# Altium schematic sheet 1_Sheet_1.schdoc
size 426 x 302 mm; Name: A_A3; Symbol: A_A3; Device: A_A3; @Project Name: FRBC - USB interface V4; REV: 4; Date: 2025-04-17; Sheet: 1/1; Draw By: JJ Shapiro; Company: SHAPIRO; Convert to PCB: yes; Add into BOM: yes; spicePre: .; @Page No: 1; @Page Count: 1; @Schematic Name: FRBC - USB interface_1; @Board Name: FRBC - USB interface_1; @Update Date: 2025-07-15; @Create Time: 17:14:42; @Update Time: 18:14:42; @Page Name: Sheet_1; @Create Date: 2025-07-15
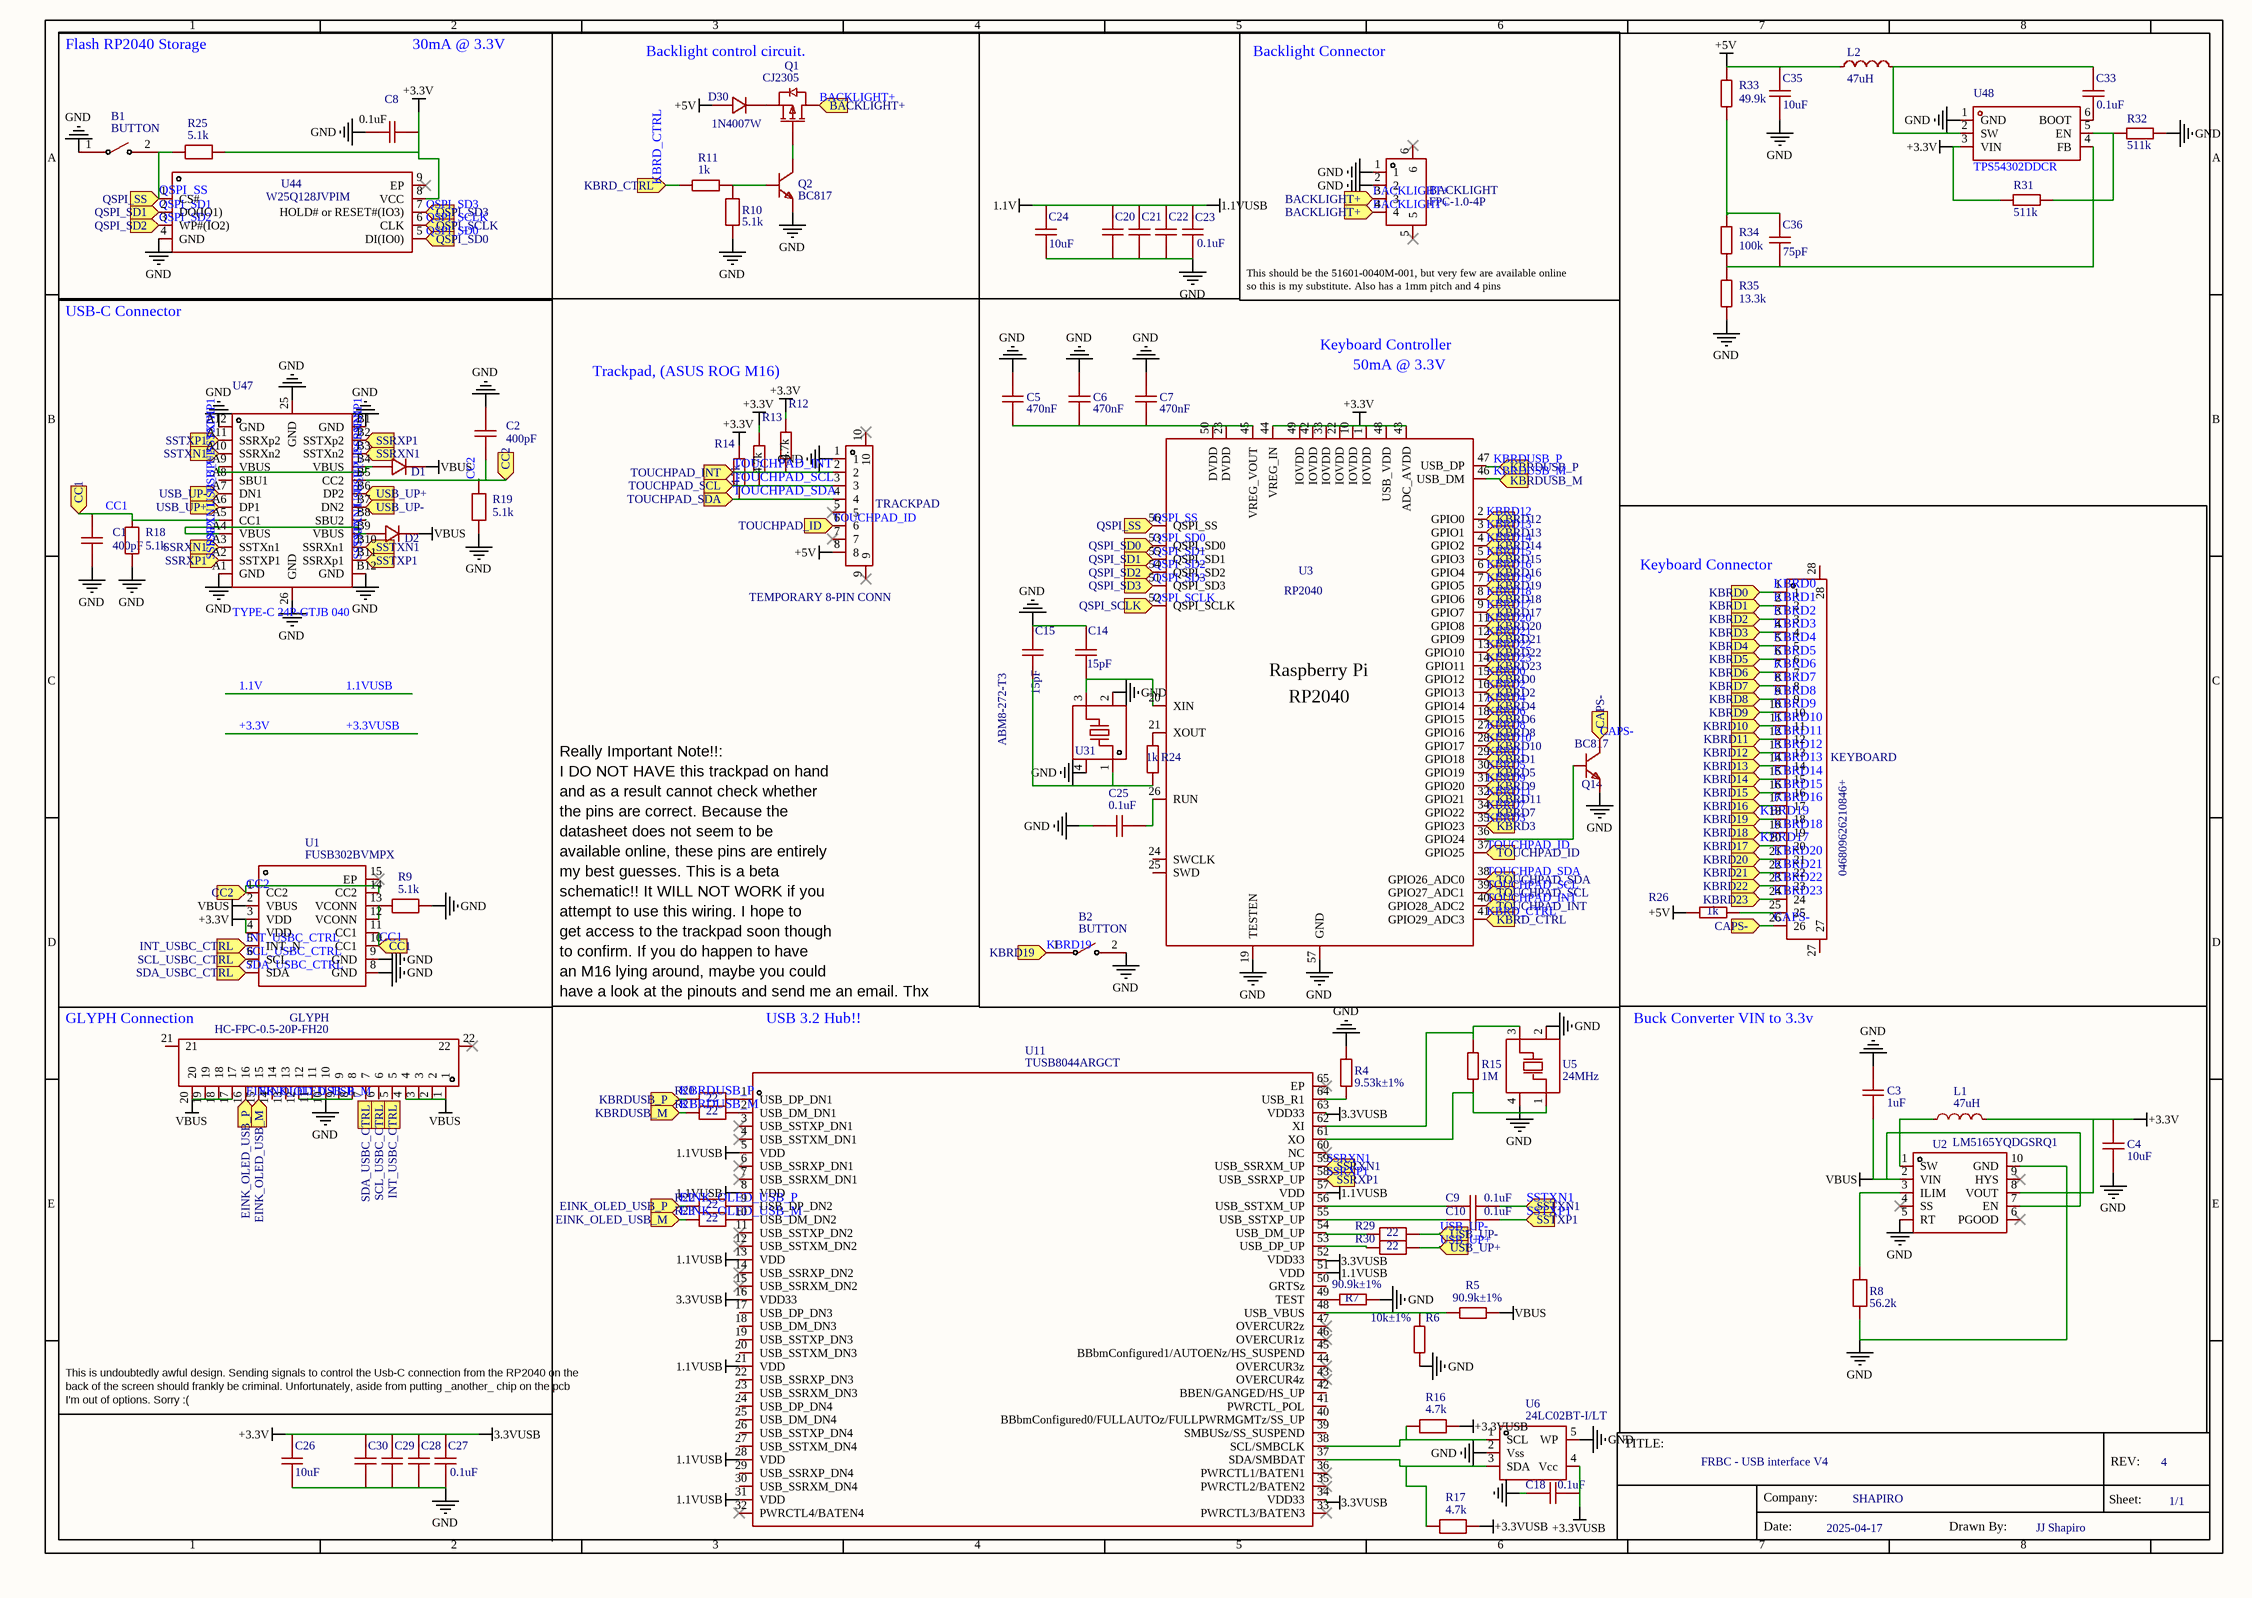
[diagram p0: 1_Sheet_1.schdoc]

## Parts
B1  BUTTON  [SW-SMD_L3.9-W2.9-LS4.9-L]
B2  BUTTON  [SW-SMD_L3.9-W2.9-LS4.9-L]
BACKLIGHT  FPC-1.0-4P  [FPC-SMD_4P-P1.00_HDGC_1.0K-ES-4PWB]
C1  400pF  [C0402]
C2  400pF  [C0402]
C3  1uF  [C0402]
C4  10uF  [C0402]
C5  470nF  [C0402]
C6  470nF  [C0402]
C7  470nF  [C0402]
C8  0.1uF  [C0402]  (value not drawn)
C9  0.1uF  [C0402]
C10  0.1uF  [C0402]
C14  15pF  [C0402]
C15  15pF  [C0402]
C18  0.1uF  [C0402]
C20  0.1uF  [C0402]  (value not drawn)
C21  0.1uF  [C0402]  (value not drawn)
C22  0.1uF  [C0402]  (value not drawn)
C23  0.1uF  [C0402]
C24  10uF  [C0402]
C25  0.1uF  [C0402]
C26  10uF  [C0402]
C27  0.1uF  [C0402]
C28  0.1uF  [C0402]  (value not drawn)
C29  0.1uF  [C0402]  (value not drawn)
C30  0.1uF  [C0402]  (value not drawn)
C33  0.1uF  [C0402]
C35  10uF  [C0402]
C36  75pF  [C0402]
D1  1N4007W  [SOD-123_L2.8-W1.8-LS3.7-RD]  (value not drawn)
D2  1N4007W  [SOD-123_L2.8-W1.8-LS3.7-RD]  (value not drawn)
D30  1N4007W  [SOD-123_L2.8-W1.8-LS3.7-RD]
GLYPH  HC-FPC-0.5-20P-FH20  [FPC-SMD_20P-P0.50_HC-FPC-0.5-20P-FH20]
KEYBOARD  046809626210846+  [FPC-SMD_26P-P0.50_046809626210846]
L1  47uH  [L0603]
L2  47uH  [L0603]
Q1  CJ2305  [SOT-23-3_L2.9-W1.3-P1.90-LS2.4-BR]
Q2  BC817  [SOT-23-3_L2.9-W1.3-P1.90-LS2.4-BR]
Q14  BC817  [SOT-23-3_L2.9-W1.3-P1.90-LS2.4-BR]
R4  9.53k±1%  [R0603]
R5  90.9k±1%  [R0603]
R6  10k±1%  [R0603]
R7  90.9k±1%  [R0603]
R8  56.2k  [R0402]
R9  5.1k  [R0402]
R10  5.1k  [R0402]
R11  1k  [R0402]
R12  4.7k - 0603  [R0402]  (value not drawn)
R13  4.7k - 0603  [R0402]  (value not drawn)
R14  4.7k  [R0402]
R15  1M  [R0603]
R16  4.7k  [R0402]
R17  4.7k  [R0402]
R18  5.1k  [R0402]
R19  5.1k  [R0402]
R20  22  [R0402]
R21  22  [R0402]
R22  22  [R0402]
R23  22  [R0402]
R24  1k  [R0402]
R25  5.1k  [R0402]
R26  1k  [R0402]
R29  22  [R0402]
R30  22  [R0402]
R31  511k  [R0603]
R32  511k  [R0603]
R33  49.9k  [R0603]
R34  100k  [R0603]
R35  13.3k  [R0603]
TRACKPAD  TEMPORARY 8-PIN CONN  [CONN-SMD_8P-P0.50_HC-FPC-0.5-8P-FHH20]
U1  FUSB302BVMPX  [MLP-14_L2.5-W2.5-P0.50-BL-EP]
U2  LM5165YQDGSRQ1  [VSSOP-10_L3.0-W3.0-P0.50-LS4.9-BL]
U3  RP2040  [LQFN-56_L7.0-W7.0-P0.4-EP]
U5  24MHz  [OSC-SMD_4P-XRCGB24M000F0L00R0]
U6  24LC02BT-I/LT  [SC-70-5_L2.0-W1.3-P0.65-LS2.1-BR]
U11  TUSB8044ARGCT  [VQFN-64_L9.0-W9.0-P0.50-TL-EP5.8]
U31  ABM8-272-T3  [CRYSTAL-SMD_4P-L3.2-W2.5-BL-2]
U44  W25Q128JVPIM  [WSON-8_L5.0-W6.0-P1.27-BL-EP]
U47  TYPE-C 24P-GTJB 040  [USB-C-SMD_TYPE-C-24P-GTJB-040]
U48  TPS54302DDCR  [SOT-23-6_L2.9-W1.6-P0.95-LS2.8-BL]

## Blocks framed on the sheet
Backlight control circuit.: D30 Q1 Q2 R10 R11
Backlight Connector: BACKLIGHT
USB-C Connector: C1 C2 D1 D2 R9 R18 R19 U1 U47
Keyboard Connector: KEYBOARD R26
Buck Converter VIN to 3.3v: C3 C4 L1 R8 U2

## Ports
BACKLIGHT+ (in), CAPS- (in), CC1 (in), CC2 (in), EINK_OLED_USB_M (in), EINK_OLED_USB_P (in), INT_USBC_CTRL (in), KBRD0 (in), KBRD1 (in), KBRD2 (in), KBRD3 (in), KBRD4 (in), KBRD5 (in), KBRD6 (in), KBRD7 (in), KBRD8 (in), KBRD9 (in), KBRD10 (in), KBRD11 (in), KBRD12 (in), KBRD13 (in), KBRD14 (in), KBRD15 (in), KBRD16 (in), KBRD17 (in), KBRD18 (in), KBRD19 (in), KBRD20 (in), KBRD21 (in), KBRD22 (in), KBRD23 (in), KBRD_CTRL (in), KBRDUSB_M (in), KBRDUSB_P (in), QSPI_SCLK (in), QSPI_SD0 (in), QSPI_SD1 (in), QSPI_SD2 (in), QSPI_SD3 (in), QSPI_SS (in), SCL_USBC_CTRL (in), SDA_USBC_CTRL (in), SSRXN1 (in), SSRXP1 (in), SSTXN1 (in), SSTXP1 (in), TOUCHPAD_ID (in), TOUCHPAD_INT (in), TOUCHPAD_SCL (in), TOUCHPAD_SDA (in), USB_UP+ (in), USB_UP- (in)

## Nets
1.1V: C20.2 C21.2 C22.2 C23.2 C24.2 U11.5(VDD) U11.8(VDD) U11.13(VDD) U11.21(VDD) U11.28(VDD) U11.31(VDD) U11.51(VDD) U11.57(VDD)  [also labelled 1.1VUSB]
+3.3V: C4.2 C8.1 C18.1 C26.2 C27.2 C28.2 C29.2 C30.2 L1.2 R12.1 R13.1 R14.1 R16.2 R17.2 R25.1 R31.2 U1.3(VDD) U1.4(VDD) U2.8(VOUT) U3.1(IOVDD) U3.10(IOVDD) U3.22(IOVDD) U3.33(IOVDD) U3.42(IOVDD) U3.43(ADC_AVDD) U3.44(VREG_IN) U3.48(USB_VDD) U3.49(IOVDD) U6.4(Vcc) U11.16(VDD33) U11.34(VDD33) U11.52(VDD33) U11.63(VDD33) U44.8(VCC) U48.3(VIN)  [also labelled +3.3VUSB, 3.3VUSB]
+5V: C35.2 D30.2 L2.1 R26.2 R33.1 TRACKPAD.8
GND: B1.1 B2.2 BACKLIGHT.1 BACKLIGHT.2 C1.1 C2.2 C3.2 C4.1 C5.2 C6.2 C7.2 C8.2 C14.1 C15.1 C18.2 C20.1 C21.1 C22.1 C23.1 C24.1 C25.2 C26.1 C27.1 C28.1 C29.1 C30.1 C35.1 GLYPH.8 GLYPH.9 GLYPH.10 GLYPH.11 GLYPH.12 Q2.2(E) Q14.2(E) R4.1 R6.2 R7.1 R8.1 R9.2 R10.1 R18.1 R19.1 R32.1 R35.2 TRACKPAD.1 U1.8(GND) U1.9(GND) U2.5(RT) U2.10(GND) U3.19(TESTEN) U3.57(GND) U5.2(GND) U5.4(GND) U6.2(Vss) U6.5(WP) U31.2(GND) U31.4(GND) U44.4(GND) U47.25(GND) U47.26(GND) U47.A1(GND) U47.A12(GND) U47.B1(GND) U47.B12(GND) U48.1(GND)
VBUS: C3.1 D1.1 D2.1 GLYPH.1 GLYPH.2 GLYPH.3 GLYPH.4 GLYPH.17 GLYPH.18 GLYPH.19 GLYPH.20 R5.1 U1.2(VBUS) U2.2(VIN) U2.7(EN)
BACKLIGHT+: BACKLIGHT.3 BACKLIGHT.4 Q1.3(D) ; port BACKLIGHT+
CAPS-: KEYBOARD.26 Q14.3(C) ; port CAPS-
CC1: C1.2 R18.2 U1.10(CC1) U1.11(CC1) U47.A5(CC1) ; port CC1
CC2: C2.1 R19.2 U1.1(CC2) U1.14(CC2) U47.B5(CC2) ; port CC2
EINK_OLED_USB_M: GLYPH.15 R23.1 ; port EINK_OLED_USB_M
EINK_OLED_USB_P: GLYPH.16 R22.1 ; port EINK_OLED_USB_P
INT_USBC_CTRL: U1.5(INT_N) ; port INT_USBC_CTRL
KBRD0: KEYBOARD.1 U3.15(GPIO12) ; port KBRD0
KBRD1: KEYBOARD.2 U3.29(GPIO18) ; port KBRD1
KBRD2: KEYBOARD.3 U3.16(GPIO13) ; port KBRD2
KBRD3: KEYBOARD.4 U3.35(GPIO23) ; port KBRD3
KBRD4: KEYBOARD.5 U3.17(GPIO14) ; port KBRD4
KBRD5: KEYBOARD.6 U3.30(GPIO19) ; port KBRD5
KBRD6: KEYBOARD.7 U3.18(GPIO15) ; port KBRD6
KBRD7: KEYBOARD.8 U3.34(GPIO22) ; port KBRD7
KBRD8: KEYBOARD.9 U3.27(GPIO16) ; port KBRD8
KBRD9: KEYBOARD.10 U3.31(GPIO20) ; port KBRD9
KBRD10: KEYBOARD.11 U3.28(GPIO17) ; port KBRD10
KBRD11: KEYBOARD.12 U3.32(GPIO21) ; port KBRD11
KBRD12: KEYBOARD.13 U3.2(GPIO0) ; port KBRD12
KBRD13: KEYBOARD.14 U3.3(GPIO1) ; port KBRD13
KBRD14: KEYBOARD.15 U3.4(GPIO2) ; port KBRD14
KBRD15: KEYBOARD.16 U3.5(GPIO3) ; port KBRD15
KBRD16: KEYBOARD.17 U3.6(GPIO4) ; port KBRD16
KBRD17: KEYBOARD.20 U3.9(GPIO7) ; port KBRD17
KBRD18: KEYBOARD.19 U3.8(GPIO6) ; port KBRD18
KBRD19: B2.1 KEYBOARD.18 U3.7(GPIO5) ; port KBRD19
KBRD20: KEYBOARD.21 U3.11(GPIO8) ; port KBRD20
KBRD21: KEYBOARD.22 U3.12(GPIO9) ; port KBRD21
KBRD22: KEYBOARD.23 U3.13(GPIO10) ; port KBRD22
KBRD23: KEYBOARD.24 U3.14(GPIO11) ; port KBRD23
KBRD_CTRL: R11.1 U3.41(GPIO29_ADC3) ; port KBRD_CTRL
KBRDUSB_M: R21.1 U3.46(USB_DM) ; port KBRDUSB_M
KBRDUSB_P: R20.1 U3.47(USB_DP) ; port KBRDUSB_P
QSPI_SCLK: U3.52(QSPI_SCLK) U44.6(CLK) ; port QSPI_SCLK
QSPI_SD0: U3.53(QSPI_SD0) U44.5(DI(IO0)) ; port QSPI_SD0
QSPI_SD1: U3.55(QSPI_SD1) U44.2(DO(IO1)) ; port QSPI_SD1
QSPI_SD2: U3.54(QSPI_SD2) U44.3(WP#(IO2)) ; port QSPI_SD2
QSPI_SD3: U3.51(QSPI_SD3) U44.7(HOLD#_or_RESET#(IO3)) ; port QSPI_SD3
QSPI_SS: B1.2 R25.2 U3.56(QSPI_SS) U44.1(CS#) ; port QSPI_SS
SCL_USBC_CTRL: U1.6(SCL) ; port SCL_USBC_CTRL
SDA_USBC_CTRL: U1.7(SDA) ; port SDA_USBC_CTRL
SSRXN1: U11.59(USB_SSRXM_UP) U47.A3(SSTXn1) U47.B3(SSTXn2) ; port SSRXN1
SSRXP1: U11.58(USB_SSRXP_UP) U47.A2(SSTXP1) U47.B2(SSTXp2) ; port SSRXP1
SSTXN1: C9.1 U47.A10(SSRXn2) U47.B10(SSRXn1) ; port SSTXN1
SSTXP1: C10.1 U47.A11(SSRXp2) U47.B11(SSRXp1) ; port SSTXP1
TOUCHPAD_ID: TRACKPAD.6 U3.37(GPIO25) ; port TOUCHPAD_ID
TOUCHPAD_INT: R12.2 TRACKPAD.2 U3.40(GPIO28_ADC2) ; port TOUCHPAD_INT
TOUCHPAD_SCL: R13.2 TRACKPAD.3 U3.39(GPIO27_ADC1) ; port TOUCHPAD_SCL
TOUCHPAD_SDA: R14.2 TRACKPAD.4 U3.38(GPIO26_ADC0) ; port TOUCHPAD_SDA
USB_UP+: R30.2 U47.A6(DP1) U47.B6(DP2) ; port USB_UP+
USB_UP-: R29.2 U47.A7(DN1) U47.B7(DN2) ; port USB_UP-
NetC5_1: C5.1 C6.1 C7.1 U3.23(DVDD) U3.45(VREG_VOUT) U3.50(DVDD)
NetC9_2: C9.2 U11.56(USB_SSTXM_UP)
NetC10_2: C10.2 U11.55(USB_SSTXP_UP)
NetC14_2: C14.2 U3.20(XIN) U31.3
NetC15_2: C15.2 R24.1 U31.1
NetC25_1: C25.1 U3.26(RUN)
NetC33_1: C33.1 U48.6(BOOT)
NetC33_2: C33.2 L2.2 U48.2(SW)
NetC36_1: C36.1 R34.2 R35.1 U48.4(FB)
NetC36_2: C36.2 R33.2 R34.1
NetD1_2: D1.2 U47.A9(VBUS) U47.B4(VBUS)
NetD2_2: D2.2 U47.A4(VBUS) U47.B9(VBUS)
NetD30_1: D30.1 Q1.2(S)
NetKEYBOARD_25: KEYBOARD.25 R26.1
NetL1_1: L1.1 U2.1(SW)
NetQ1_1: Q1.1(G) Q2.3(C)
NetQ2_1: Q2.1(B) R10.2 R11.2
NetQ14_1: Q14.1(B) U3.36(GPIO24)
NetR4_2: R4.2 U11.64(USB_R1)
NetR5_2: R5.2 R6.1 U11.48(USB_VBUS)
NetR7_2: R7.2 U11.49(TEST)
NetR8_2: R8.2 U2.3(ILIM)
NetR9_1: R9.1 U1.12(VCONN) U1.13(VCONN)
NetR15_1: R15.1 U5.3(OSC2) U11.62(XI)
NetR15_2: R15.2 U5.1(OSC1) U11.61(XO)
NetR16_1: R16.1 U6.1(SCL) U11.38(SCL/SMBCLK)
NetR17_1: R17.1 U6.3(SDA) U11.37(SDA/SMBDAT)
NetR20_2: R20.2 U11.1(USB_DP_DN1)
NetR21_2: R21.2 U11.2(USB_DM_DN1)
NetR22_2: R22.2 U11.9(USB_DP_DN2)
NetR23_2: R23.2 U11.10(USB_DM_DN2)
NetR24_2: R24.2 U3.21(XOUT)
NetR29_1: R29.1 U11.54(USB_DM_UP)
NetR30_1: R30.1 U11.53(USB_DP_UP)
NetR31_1: R31.1 R32.2 U48.5(EN)

Not connected (* = marked no-connect by the designer): BACKLIGHT 5* 6*; GLYPH 5 6 7 13 14 21 22*; KEYBOARD 27 28; TRACKPAD 5* 7* 9* 10*; U1 15(EP)*; U2 4(SS)* 6(PGOOD)* 9(HYS)*; U3 24(SWCLK) 25(SWD); U11 3(USB_SSTXP_DN1)* 4(USB_SSTXM_DN1)* 6(USB_SSRXP_DN1)* 7(USB_SSRXM_DN1)* 11(USB_SSTXP_DN2)* 12(USB_SSTXM_DN2)* 14(USB_SSRXP_DN2)* 15(USB_SSRXM_DN2)* 17(USB_DP_DN3) 18(USB_DM_DN3) 19(USB_SSTXP_DN3) 20(USB_SSTXM_DN3) 22(USB_SSRXP_DN3) 23(USB_SSRXM_DN3) 24(USB_DP_DN4) 25(USB_DM_DN4) 26(USB_SSTXP_DN4) 27(USB_SSTXM_DN4) 29(USB_SSRXP_DN4) 30(USB_SSRXM_DN4) 32(PWRCTL4/BATEN4)* 33(PWRCTL3/BATEN3)* 35(PWRCTL2/BATEN2)* 36(PWRCTL1/BATEN1)* 39(SMBUSz/SS_SUSPEND) 40(BBbmConfigured0/FULLAUTOz/FULLPWRMGMTz/SS_UP) 41(PWRCTL_POL) 42(BBEN/GANGED/HS_UP) 43(OVERCUR4z)* 44(OVERCUR3z)* 45(BBbmConfigured1/AUTOENz/HS_SUSPEND) 46(OVERCUR1z)* 47(OVERCUR2z)* 50(GRTSz) 60(NC)* 65(EP)*; U44 9(EP)*; U47 A8(SBU1) B8(SBU2)

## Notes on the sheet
- Flash RP2040 Storage
- 30mA @ 3.3V
- (near C8) 0.1uF
- This should be the 51601-0040M-001, but very few are available online
- so this is my substitute. Also has a 1mm pitch and 4 pins
- Keyboard Controller
- Trackpad, (ASUS ROG M16)
- 50mA @ 3.3V
- (near R13) 4.7k
- (near R12) 4.7k
- the pins are correct. Because the
- and as a result cannot check whether
- I DO NOT HAVE this trackpad on hand
- Really Important Note!!:
- my best guesses. This is a beta
- available online, these pins are entirely
- datasheet does not seem to be
- get access to the trackpad soon though
- attempt to use this wiring. I hope to
- schematic!! It WILL NOT WORK if you
- have a look at the pinouts and send me an email. Thx
- an M16 lying around, maybe you could
- to confirm. If you do happen to have
- (near GLYPH) GLYPH Connection
- USB 3.2 Hub!!
- This is undoubtedly awful design. Sending signals to control the Usb-C connection from the RP2040 on the
- back of the screen should frankly be criminal. Unfortunately, aside from putting _another_ chip on the pcb
- I'm out of options. Sorry :(

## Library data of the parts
B1 B2 = BUTTON: Manufacturer: null; Convert to PCB: yes; Contributor: lcsc
BACKLIGHT = FPC-1.0-4P: Manufacturer: null; Convert to PCB: yes; Contributor: LCSC
C1 C2 = 400pF: Convert to PCB: yes; nameAlias: Value(F); Contributor: LCEDA_Lib
C3 = 1uF: Convert to PCB: yes; nameAlias: Value(F); Contributor: LCEDA_Lib
C4 C24 C26 C33 C35 C36 = 10uF: Convert to PCB: yes; nameAlias: Value(F); Contributor: LCEDA_Lib
C5-C7 = 470nF: Convert to PCB: yes; nameAlias: Value; Contributor: lcsc
C8-C10 C18 C20-C23 C25 C27-C30 = 0.1uF: Convert to PCB: yes; nameAlias: Value(F); Contributor: LCEDA_Lib
C14 C15 = 15pF: Manufacturer: null; Manufacturer Part: 0201; Convert to PCB: yes; Contributor: lcsc
D1 D2 D30 = 1N4007W: Manufacturer: BLUE ROCKET; Convert to PCB: yes; Contributor: LCEDA_Lib
GLYPH = HC-FPC-0.5-20P-FH20: Manufacturer: HC(虹成电子); Convert to PCB: yes; Contributor: lcsc
KEYBOARD = 046809626210846+: Manufacturer: Kyocera AVX; Convert to PCB: yes; Contributor: lcsc
L1 L2 = 47uH: Convert to PCB: yes; nameAlias: Value(H); Contributor: LCEDA_Lib
Q1 = CJ2305: Manufacturer: CJ(江苏长电/长晶); Convert to PCB: yes
Q2 Q14 = BC817: Manufacturer: CJ(江苏长电/长晶); Manufacturer Part: BC817-40(RANGE:250-600); Convert to PCB: yes
R4 = 9.53k±1%: Convert to PCB: yes; nameAlias: Value; Contributor: LCSC
R5 R7 = 90.9k±1%: Convert to PCB: yes; nameAlias: Value; Contributor: LCSC
R6 = 10k±1%: Convert to PCB: yes; nameAlias: Value; Contributor: LCSC
R8 = 56.2k: Convert to PCB: yes; nameAlias: Value(Ω); Contributor: LCEDA_Lib
R9 R10 R18 R19 R25 = 5.1k: Convert to PCB: yes; nameAlias: Value(Ω); Contributor: LCEDA_Lib
R11 R24 R26 = 1k: Convert to PCB: yes; nameAlias: Value; Contributor: LCSC
R12 R13 = 4.7k - 0603: Convert to PCB: yes; nameAlias: Value; Contributor: LCSC
R14 = 4.7k: Convert to PCB: yes; nameAlias: Value; Contributor: LCSC
R15 R31-R35 = 1M: Convert to PCB: yes; nameAlias: Value; Contributor: LCSC
R16 R17 = 4.7k: Convert to PCB: yes; nameAlias: Value(Ω); Contributor: LCEDA_Lib
R20-R23 R29 R30 = 22: Convert to PCB: yes; nameAlias: Value(Ω); Contributor: LCEDA_Lib
TRACKPAD = TEMPORARY 8-PIN CONN: Manufacturer: HC(虹成电子); Manufacturer Part: HC-FPC-0.5-8P-FHH20; Convert to PCB: yes; Contributor: lcsc
U1 = FUSB302BVMPX: Manufacturer: onsemi(安森美); Convert to PCB: yes; Contributor: LCSC
U2 = LM5165YQDGSRQ1: Manufacturer: TI(德州仪器); Convert to PCB: yes; Contributor: LCSC
U3 = RP2040: Manufacturer: Raspberry Pi(树莓派); Convert to PCB: yes; Contributor: LCSC
U5 = 24MHz: Manufacturer: muRata(村田); Manufacturer Part: XRCGB24M000F1H17R0; Convert to PCB: yes; Contributor: lcsc; nameAlias: Value
U6 = 24LC02BT-I/LT: Manufacturer: MICROCHIP(美国微芯); Convert to PCB: yes; Contributor: lcsc
U11 = TUSB8044ARGCT: Manufacturer: TI(德州仪器); Convert to PCB: yes; Contributor: lcsc
U31 = ABM8-272-T3: Manufacturer: null; Convert to PCB: yes; Contributor: lcsc
U44 = W25Q128JVPIM: Manufacturer: WINBOND(华邦); Convert to PCB: yes; Contributor: LCSC
U47 = TYPE-C 24P-GTJB 040: Manufacturer: SHOU HAN(首韩); Add into BOM: yes; Gender: Male; Number of Contacts: 24P; Number of Ports: 1; Current Rating - Power (Max): 5A; Rated Voltage (Max): 20V; Connect-Disconnect Life: 10,000 times; Core Colour: Black
U48 = TPS54302DDCR_C311983: Manufacturer: TI(德州仪器); Add into BOM: yes; Function: Step-down type; Output Type: Fixed; Input Voltage: 4.5V~28V; Output Voltage: 5V; Output Current: 3A; Switching Frequency: 400kHz; Number of Outputs: 1; Topology: Step-down; Quiescent Current (Iq): 45uA; Switch tube (built-in/external): Built-in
